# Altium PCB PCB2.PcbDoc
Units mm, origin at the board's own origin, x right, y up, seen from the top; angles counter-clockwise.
Board outline 35.25 x 52.55 mm, 2 copper layers (Top Layer, Bottom Layer); 25 components, 21 nets, 77 pads, 4 vias.
Unrouted connection lines stored in the file: 1.
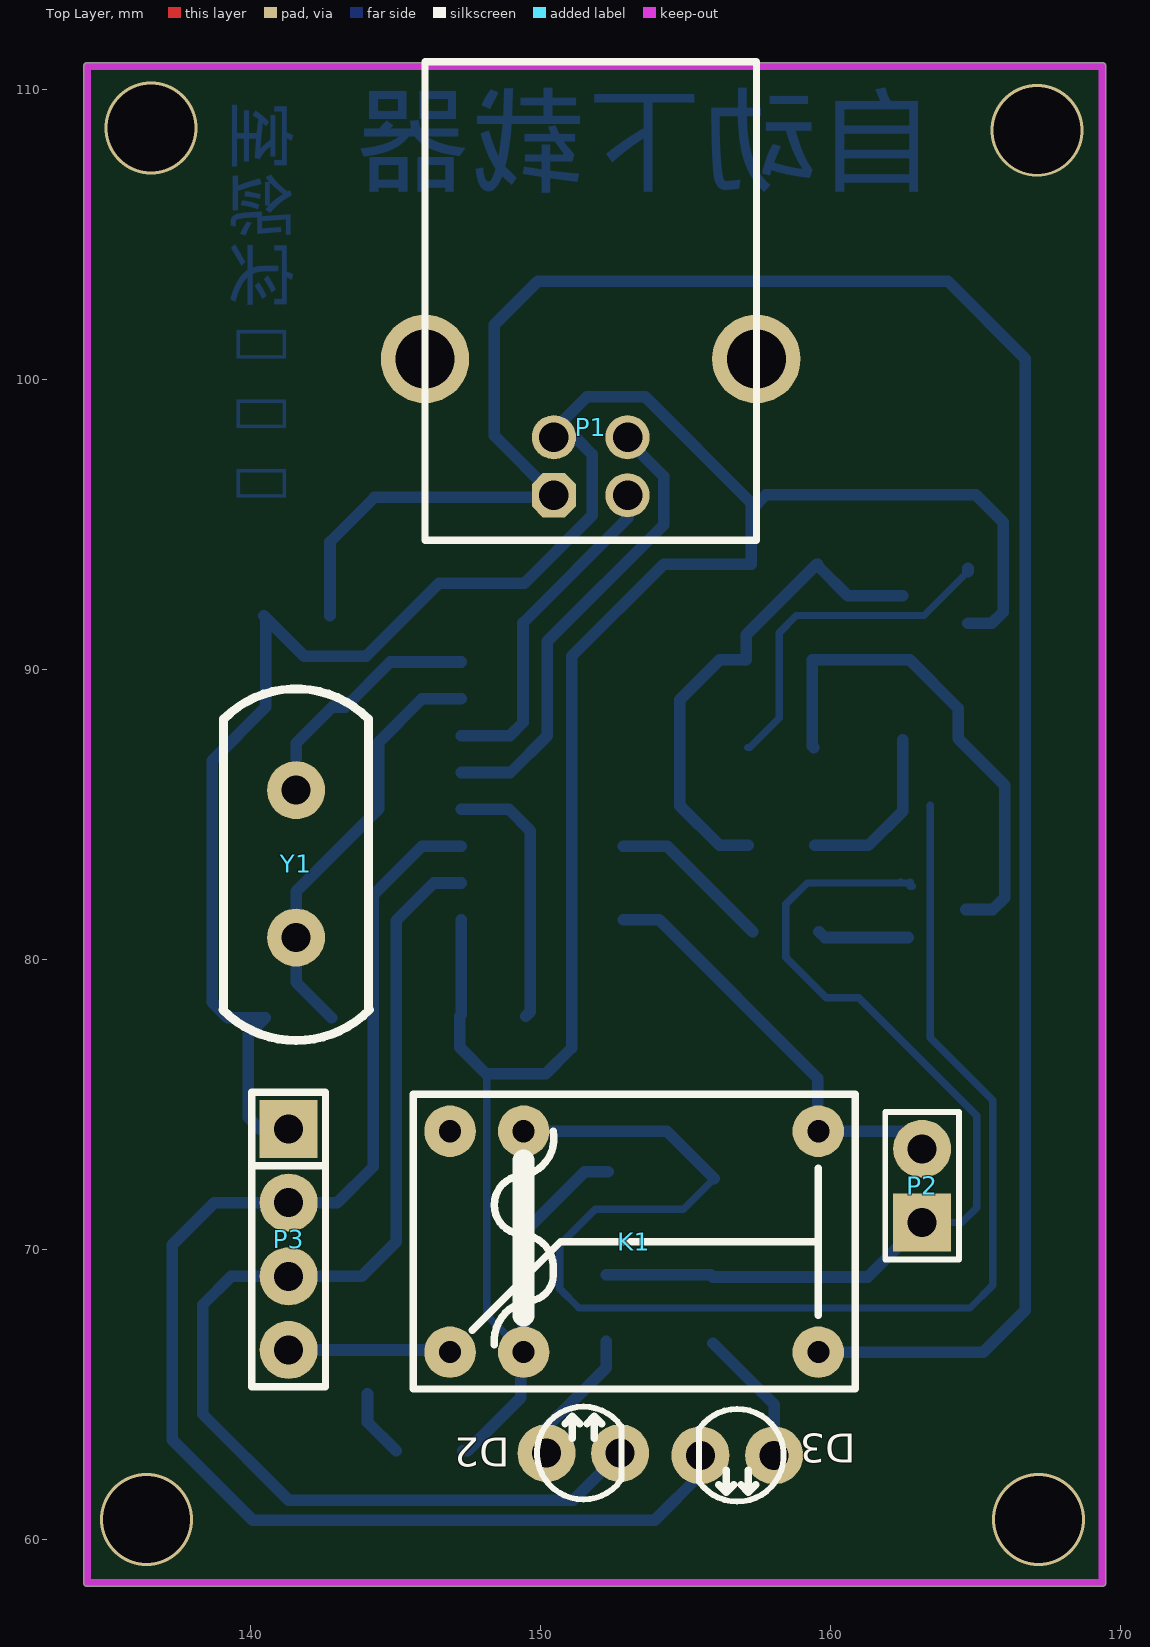
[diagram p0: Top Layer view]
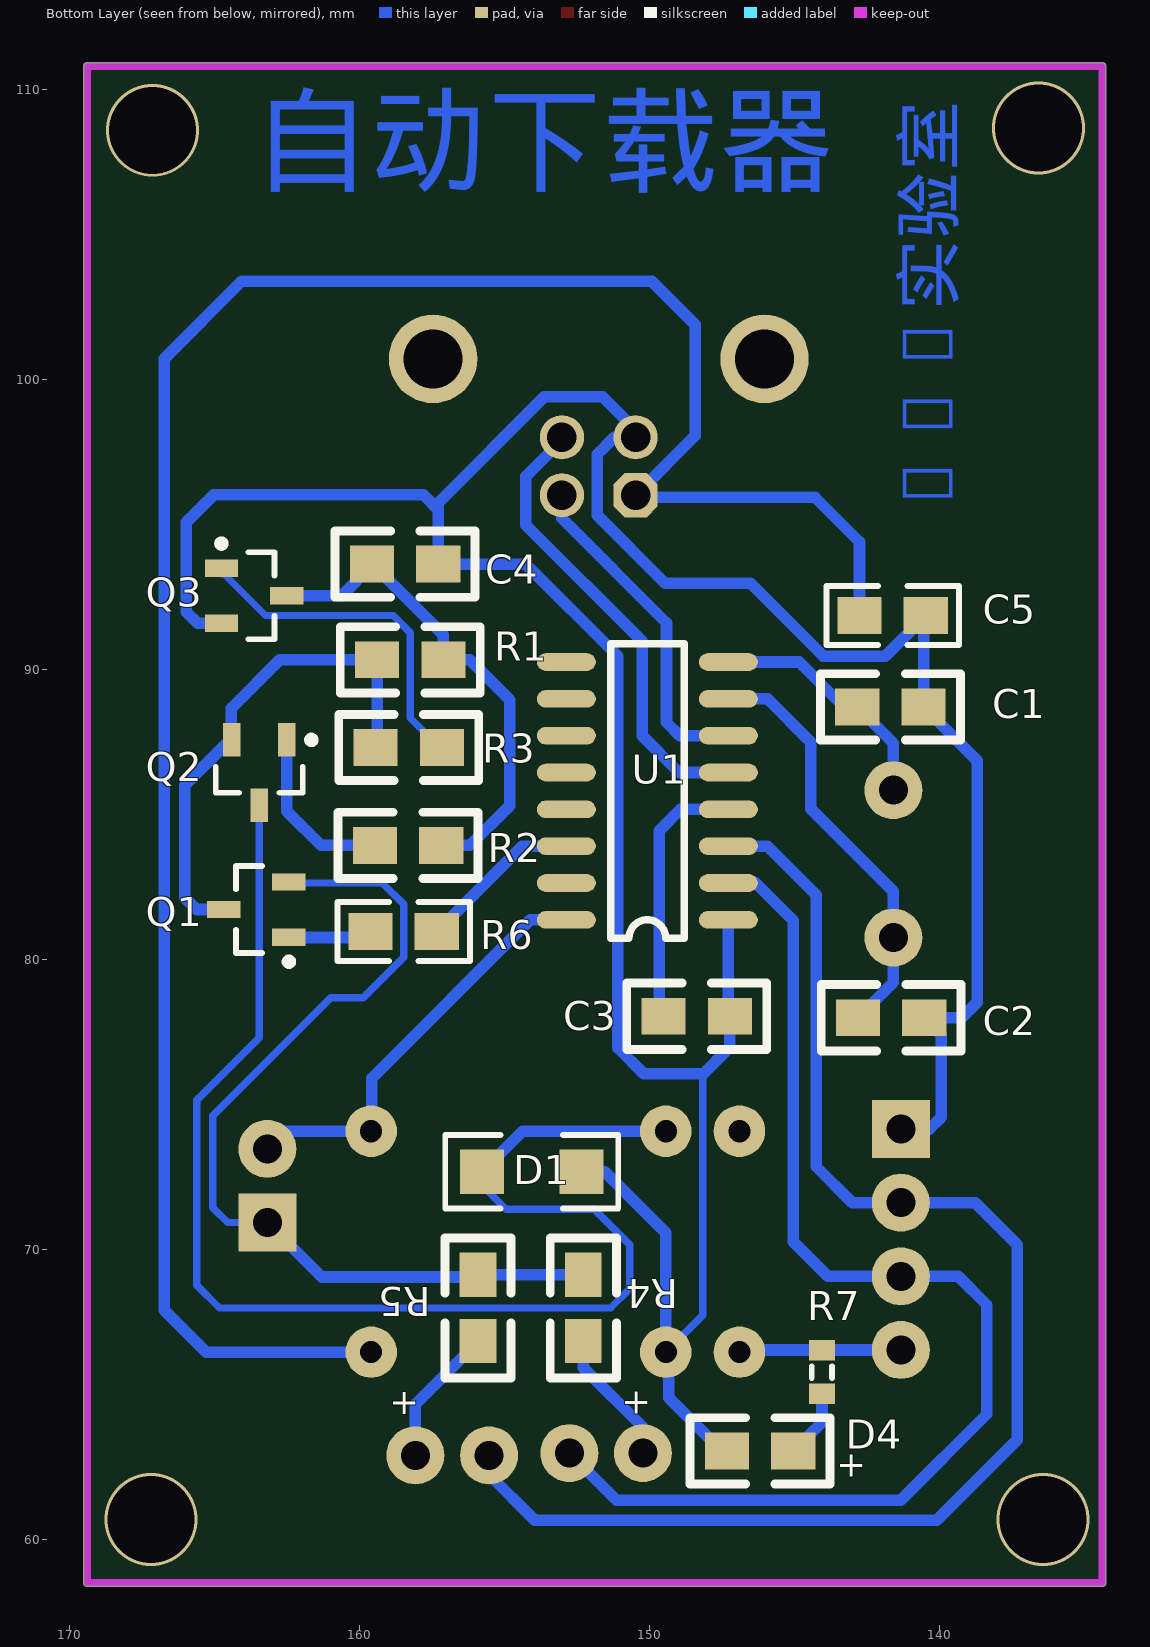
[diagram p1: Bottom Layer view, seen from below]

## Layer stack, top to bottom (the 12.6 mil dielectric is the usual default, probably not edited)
Top Layer: signal copper 0.0356
Dielectric: dielectric 0.32, FR-4, Dk 4.8
Bottom Layer: signal copper 0.0356

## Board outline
134.379,58.394 cw(c134.379,58.522) 134.251,58.522 134.251,110.813 cw(c134.379,110.813) 134.379,110.94 169.379,110.94 cw(c169.379,110.813) 169.506,110.813 169.506,58.522 cw(c169.379,58.522) 169.379,58.394

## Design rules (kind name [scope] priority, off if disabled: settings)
Clearance [All] p1: gap=0.254
PolygonConnect [All] p1: connectstyle=Relief reliefconductorwidth=0.254 reliefentries=4 polygonreliefangle="90 Angle" airgapwidth=0.254
RoutingVias [All] p1: holewidth=0.711 width=1.27 viastyle="Through Hole" minholewidth=0.711 minwidth=1.27 maxholewidth=0.711 maxwidth=1.27
SolderMaskExpansion [All] p1: expansion=0.102
Width [All] p1: maxlimit=0.5 minlimit=0.254 preferedwidth=0.254
28 further rules are at their usual default settings.

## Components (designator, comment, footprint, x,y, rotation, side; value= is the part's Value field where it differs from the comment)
C1 "Cap" 0805 142.824,88.722 r180 bottom
C2 "Cap" 0805 140.513,78.003 r0 bottom
C3 "Cap" 0805 147.218,78.054 r0 bottom
C4 "Cap" 0805 157.277,93.65 r0 bottom
C5 "Cap Pol1" 0805_RES 141.605,91.872 r180 bottom
D1 "Diode" 1206 154.051,72.695 r0 bottom
D2 "LED0" LED_3MM 151.486,62.992 r0 top
D3 "LED0" LED_3MM 156.794,62.916 r180 top
D4 "LED3" 0805 145.034,63.068 r0 bottom
K1 "Relay-SPDT" RELAY5V 153.492,74.6 r270 top
P1 "Header 4" USB_2 151.74,98.374 r90 top
P2 "Header 2" HDR1X2 163.17,70.942 r90 top
P3 "Header 4" SIP4 141.326,70.358 r270 top
Q1 "PNP" SOT-23B_N 163.551,81.737 r0 bottom
Q2 "PNP" SOT-23B_N 163.449,86.462 r270 bottom
Q3 "QNPN" SOT-23B_N 163.627,92.558 r180 bottom
R1 "Res2" 0805 157.099,90.348 r0 bottom
R2 "Res2" 0805 159.461,83.947 r180 bottom
R3 "Res0" 0805 157.15,87.325 r0 bottom
R4 "Res2" 0805 152.273,66.853 r90 bottom
R5 "Res2" 0805 155.905,66.853 r90 bottom
R6 "Res3" 0805_RES 158.471,80.975 r180 bottom
R7 "Res3" J1-0603 144.043,65.786 r270 bottom
U1 "CH340G" SOP16 150.063,85.827 r0 bottom
Y1 "XTAL" XTAL 141.58,83.312 r90 top

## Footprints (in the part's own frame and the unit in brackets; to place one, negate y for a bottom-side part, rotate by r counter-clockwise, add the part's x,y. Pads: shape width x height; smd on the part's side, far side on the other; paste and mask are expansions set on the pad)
0805 [mil]
  rect 60x50 smd: 1(0,0) 2(90,0)
  silkscreen extent -50,-45 140,45
0805_RES [mil]
  rect 60x50 smd: 1(-45,0) 2(45,0)
  silkscreen extent -90,-40 90,40
1206 [mil]
  rect 60x60 smd: 1(-67.5,0) 2(67.5,0)
  silkscreen extent -118,-50 118,50
HDR1X2 [mm] "Connector; Header; 2 Position"
  rect 2x2 hole 1: 1(0,0)
  round 2 hole 1: 2(2.54,0)
  silkscreen extent -1.27,-1.27 3.81,1.27
J1-0603 [mm] "Chip Resistor, Body 1.6x0.8mm, IPC High Density"
  rect 0.7x0.9 smd: 1(-0.75,0) 2(0.75,0)
  silkscreen extent -0.2,-0.35 0.2,0.35, body extent -0.85,-0.48 0.85,0.48, height 0.9
LED_3MM [mm]
  round 2 hole 1: 1(-1.27,0) 2(1.27,0)
  silkscreen extent -1.6,-1.6 1.32,1.6
RELAY5V [mil]
  round 70 hole 30: 1(20,240) 1(320,240) 2(20,-260) 3(320,-260) 4(20,-160) 5(320,-160)
  silkscreen extent -30,-310 370,290
SIP4 [mm]
  rect 2x2 hole 1: 1(-3.81,0)
  round 2 hole 1: 2(-1.27,0) 3(1.27,0) 4(3.81,0)
  silkscreen extent -5.08,-1.27 5.08,1.27
SOP16 [mil]
  oval 80x24 smd: 1(-110,175) 2(-110,125) 3(-110,75) 4(-110,25) 5(-110,-25) 6(-110,-75) 7(-110,-125) 8(-110,-175) 9(110,-175) 10(110,-125) 11(110,-75) 12(110,-25) 13(110,25) 14(110,75) 15(110,125) 16(110,175)
  silkscreen extent -50,-200 50,200
SOT-23B_N [mm] "SOT23, 3-Leads, Body 2.9x1.3mm, Pitch 0.95mm, Lead Span 2.4mm, IPC Medium Density"
  rect 1.15x0.6 smd: 1(-1.125,0.95) 2(-1.125,-0.95) 3(1.125,0)
  silkscreen extent -1.25,-1.5 0.7,1.92, body extent -0.7,-1.5 0.7,1.5, height 1.14
USB_2 [mil]
  oct 60x60 hole 40: 1(-92.52,50)
  round 60 hole 40: 2(-92.52,-50) 3(-13.78,-50) 4(-13.78,50)
  round 120 hole 80: 5(92.52,225) 6(92.52,-225)
  silkscreen extent -154,-225 496,225
XTAL [mm]
  round 2 hole 1: 1(-2.54,0) 2(2.54,0)
  silkscreen extent -6.09,-2.53 6.03,2.53

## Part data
C1 C2 C3 C4: "Capacitor"
C5: "Polarized Capacitor (Radial)"
D1: "Default Diode"
D2 D3: "Typical INFRARED GaAs LED"
D4: "Typical BLUE SiC LED"
K1: "Single-Pole Dual-Throw Relay"
P1 P3: "Header, 4-Pin"
P2: "Header, 2-Pin"
Q1 Q2: "PNP Bipolar Transistor"
Q3: "NPN Bipolar Transistor"
R1 R2 R4 R5 R6 R7: "Resistor"
R3: library part Res2, "Resistor"
Y1: "Crystal Oscillator"

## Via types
v1: diameter 3.2, hole 3, Top Layer to Bottom Layer, 4 vias

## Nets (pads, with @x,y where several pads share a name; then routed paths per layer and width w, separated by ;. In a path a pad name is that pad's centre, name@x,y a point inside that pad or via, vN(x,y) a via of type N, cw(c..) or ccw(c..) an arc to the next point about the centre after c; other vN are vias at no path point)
C: Q3.1 R3.1 | length 12
  Bottom Layer w0.245: R3.1 R3.1@157.226,87.325
  Bottom Layer w0.254: R3.1@157.226,87.325 158.242,88.341 158.242,91.288 158.831,91.877 163.235,91.877 Q3.1@164.752,93.394
  Bottom Layer w0.4: Q3.1@164.752,93.394 Q3.1
D+: P1.3 U1.5 | length 15.9
  Bottom Layer w0.4: U1.5 148.971,86.462 150.241,87.732 150.241,90.983 154.254,94.996 154.254,96.672 P1.3@152.979,97.948
D-: P1.2 U1.6 | length 11.7
  Bottom Layer w0.4: U1.6 148.946,87.732 149.403,88.189 149.403,91.618 153.01,95.225 P1.2
GND: C1.2 C2.1 C3.1 C4.1 C5.2 D1.1 D4.2 K1.5 P1.4 P3.1 Q3.2 U1.1 | length 116.1
  Bottom Layer w0.254: 148.158,76.073 148.158,67.742 K1.5@149.327,66.573
  Bottom Layer w0.4: C5.2 C5.2@140.538,91.796 ; P3.1 140.335,74.168 139.929,74.574 139.929,77.419 C2.1 139.217,78.003 138.684,78.537 138.684,86.868 C1.2 C5.2@140.538,91.796 ; U1.1 147.269,78.105 C3.1 147.218,76.987 148.158,76.048 ; D4.2 147.498,63.068 149.327,64.897 149.327,66.573 149.428,66.675 149.428,70.587 151.536,72.695 D1.1 ; 148.158,76.073 150.19,76.073 151.079,76.962 151.079,90.475 154.254,93.65 C4.1 157.277,95.529 ; Q3.2 165.572,91.608 165.964,91.999 165.964,95.098 165.024,96.037 157.785,96.037 157.277,95.529 ; C5.2@140.538,91.796 141.859,90.475 143.993,90.475 146.507,92.989 149.454,92.989 151.794,95.329 151.794,97.431 151.201,98.024 P1.4 150.47,98.273 151.613,99.416 153.619,99.416 157.277,95.758 157.277,95.529
NetC4_2: C4.2 Q3.3 R1.1 R2.2 | length 17.2
  Bottom Layer w0.4: R2.2 156.185,83.947 154.813,85.319 154.813,88.976 156.185,90.348 R1.1 157.099,91.211 159.537,93.65 C4.2 159.563,93.599 160.604,92.558 Q3.3
NetD1_2: D1.2 K1.4 Q2.3 | length 48
  Bottom Layer w0.254: D1.2@156,72.46 154.94,71.399 151.892,71.399 150.673,70.18 150.673,68.656 151.333,67.996 164.821,67.996 165.608,68.783 165.608,75.159 163.449,77.318 Q2.3
  Bottom Layer w0.4: K1.4 154.368,74.092 D1.2 D1.2@156,72.46
NetD2_1: D2.1 R4.1 | length 4.7
  Bottom Layer w0.4: D2.1 150.216,63.881 152.273,65.938 R4.1
NetD3_1: D3.1 R5.1 | length 4.8
  Bottom Layer w0.4: R5.1@155.956,66.777 158.064,64.668 158.064,62.84 D3.1@158.09,62.814
NetD4_1: D4.1 R7.2 | length 2.4
  Bottom Layer w0.4: R7.2 144.043,64.059 D4.1
NetQ1_1: Q1.1 R6.1 | length 3.2
  Bottom Layer w0.4: R6.1 159.817,80.772 Q1.1@162.695,80.772
NetQ1_3: Q1.3 Q2.2 R1.2 R3.2 | length 18.2
  Bottom Layer w0.254: R3.2 159.436,88.011
  Bottom Layer w0.4: R3.2 159.385,87.376 R1.2 162.738,90.348 164.414,88.671 164.414,87.622 166.014,86.022 166.014,83.007 166.014,82.144 165.608,81.737 Q1.3
NetQ2_1: Q2.1 R2.1 | length 6
  Bottom Layer w0.4: R2.1 161.315,83.947 162.499,85.131 Q2.1
PWR: K1.3 P3.4 R7.1 | length 5.5
  Bottom Layer w0.4: P3.4 K1.3@146.812,66.548
RTS: R6.2 U1.14 | length 5.7
  Bottom Layer w0.4: U1.14 154.381,83.922 R6.2
RXD: D2.2 P3.3 U1.2 | length 41.5
  Bottom Layer w0.4: U1.2 146.329,82.652 145.034,81.356 145.034,70.282 143.84,69.088 P3.3 139.344,69.088 138.354,68.097 138.354,64.338 141.326,61.366 151.13,61.366 D2.2
TXD: D3.2 P3.2 U1.3 | length 48.5
  Bottom Layer w0.4: U1.3 145.923,83.922 144.247,82.245 144.247,72.873 143.002,71.628 P3.2 138.76,71.628 137.312,70.18 137.312,63.449 140.081,60.681 153.949,60.681 155.524,62.255 D3.2
V3: C3.2 U1.4 | length 9.2
  Bottom Layer w0.4: U1.4 148.92,85.192 149.657,84.455 149.657,78.207 C3.2
VCC: C5.1 K1.1 P1.1 P2.2 U1.16 | length 92.9
  Bottom Layer w0.4: C5.1 142.748,94.412 144.284,95.948 150.393,95.948 P1.1 148.412,98.082 148.412,101.905 149.911,103.403 164.059,103.403 166.726,100.736 166.726,67.92 165.278,66.472 K1.1@159.588,66.472 ; U1.16 154.102,81.382 159.563,75.921 159.563,74.117 K1.1@159.537,74.092 ; K1.1@159.588,74.092 162.56,74.092 P2.2
VDD: P2.1 Q1.2 R4.2 R5.2 | length 32.6
  Bottom Layer w0.254: Q1.2@162.408,82.687 Q1.2 ; Q1.2@162.763,82.687 162.763,82.535 162.832,82.535 162.715,82.652 159.207,82.652 158.471,81.915 158.471,80.086 159.868,78.689 160.985,78.689 165.049,74.625 165.049,71.45 164.541,70.942 P2.1
  Bottom Layer w0.4: R4.2 155.88,69.139 155.956,69.063 161.29,69.063 P2.1
XI: C2.2 U1.7 Y1.1 | length 14.6
  Bottom Layer w0.4: C2.2 141.58,79.223 Y1.1 141.58,82.372 144.424,85.217 144.424,87.503 145.923,89.002 U1.7
XO: C1.1 U1.8 Y1.2 | length 8.5
  Bottom Layer w0.4: Y1.2 141.58,87.478 C1.1 143.281,88.722 144.831,90.272 U1.8
pads on no net: K1.2 P1.5 P1.6 U1.9 U1.10 U1.11 U1.12 U1.13 U1.15
copper on no net:
  other v1: 136.423,60.706 167.183,60.706 167.132,108.61 136.576,108.687

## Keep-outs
Keep-Out Layer:
  lines w0.254: 134.379,58.522 134.379,110.813 169.379,110.813 169.379,58.522 134.379,58.522

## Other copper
Bottom Layer:
  text "自动下载器" at 163.601,105.867 h5
  text "208实验室" at 138.938,95.225 h3 r270

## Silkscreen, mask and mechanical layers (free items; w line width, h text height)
Bottom Overlay:
  text "+" at 149.936,64.059 h1.52
  text "+" at 157.937,64.033 h1.52
  text "+" at 142.519,61.874 h1.52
